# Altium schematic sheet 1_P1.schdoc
size 307 x 218 mm; Symbol: Drawing-Symbol_A4; Device: Drawing-Symbol_A4; @Project Name: OpenSteamDeck ButtonPCB; @Page Count: 1; @Update Date: 2025-07-23; @Create Date: 2025-07-02; @Schematic Name: Schematic1; @Page No: 1; @Page Name: P1; Company: EasyEDA.com; Version: V1.0; Page Size: A4; @Create Time: 10:19:51; @Update Time: 22:36:55; Width: 1170; Height: 825; Region Start: 1; X Region Count: 6; Y Region Count: 4; Blade Width: 10; Title Block Position: 3; @Board Name: Board1
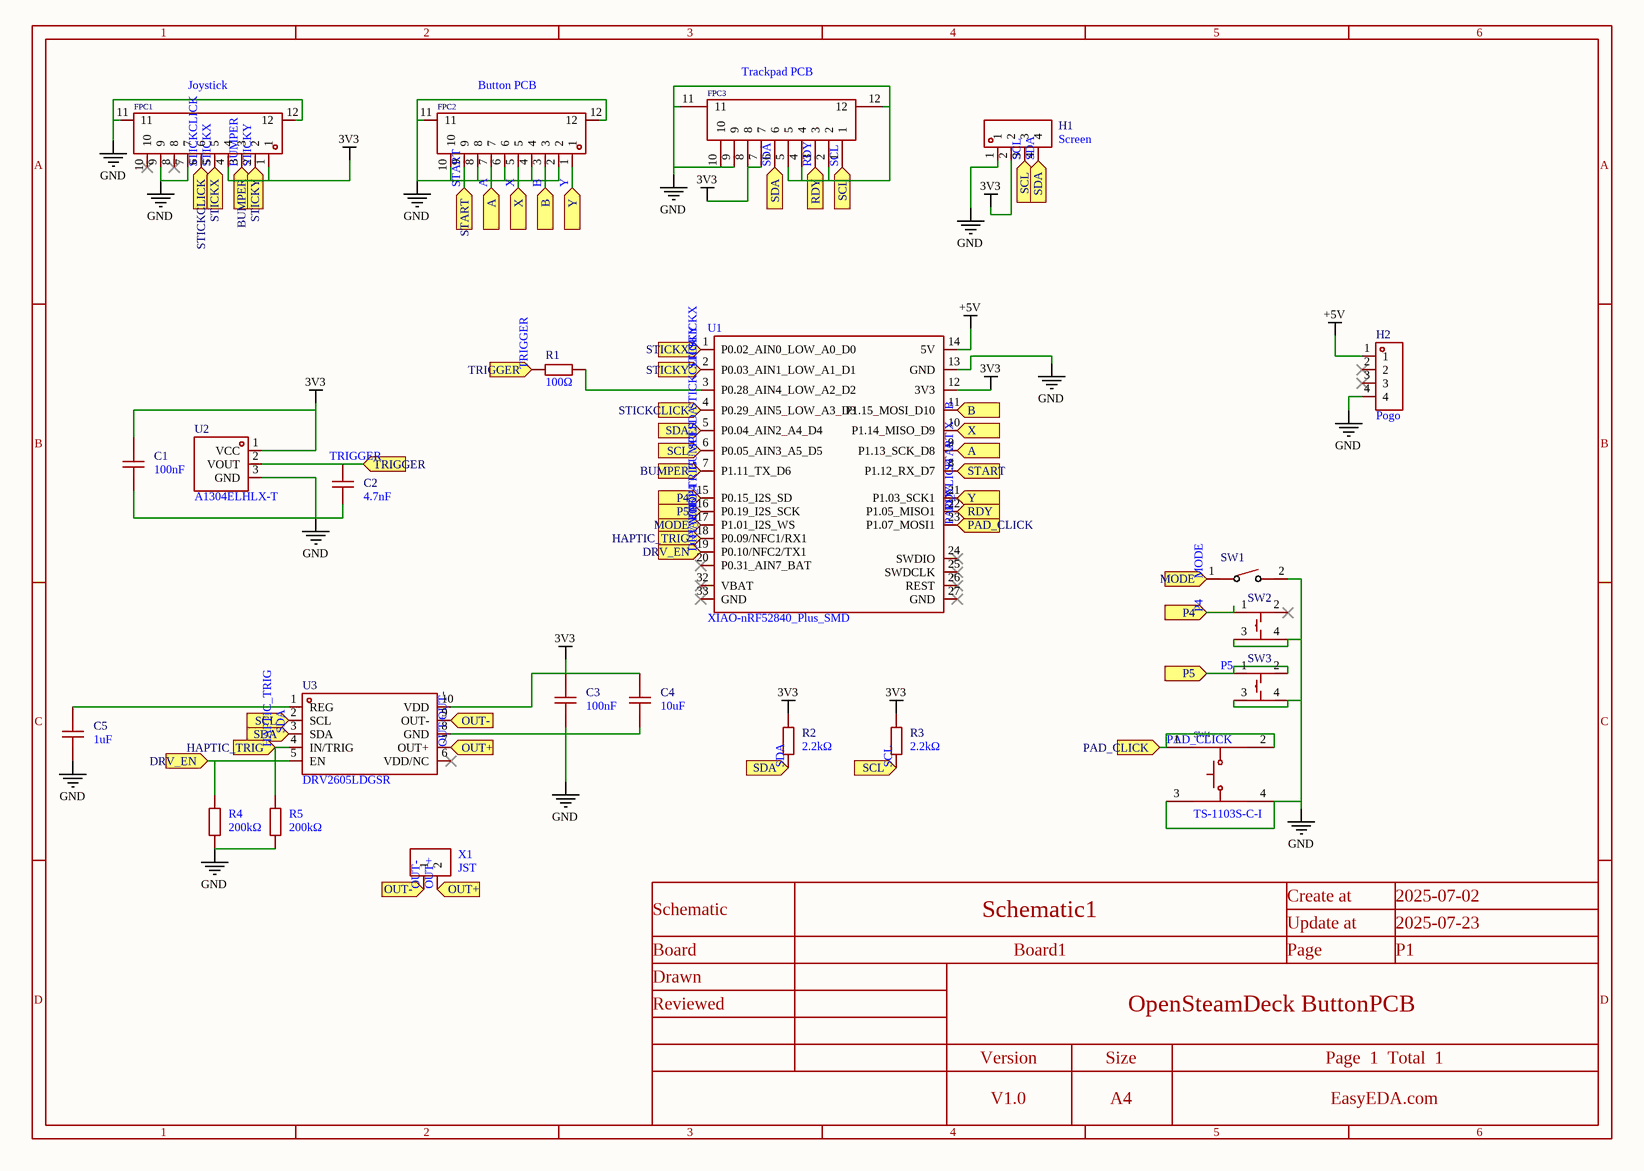
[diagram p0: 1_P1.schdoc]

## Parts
C1  100nF  [C0603]
C2  4.7nF  [C0603]
C3  100nF  [C0603]
C4  10uF  [C0603]
C5  1uF  [C0603]
FPC1  Joystick  [FPC-SMD_10P-P0.50_XUNPU_FPC-05F-10PH15]
FPC2  Button PCB  [FPC-SMD_10P-P0.50_XUNPU_FPC-05F-10PH15]
FPC3  Trackpad PCB  [FPC-SMD_P0.50-10P_LCS-SJ-H2.0]
H1  Screen  [HDR-TH_4P-P2.54-V-F]
H2  Pogo  [HDR-TH_4P-P2.54-V-F]
R1  100Ω  [R0603]
R2  2.2kΩ  [R0603]
R3  2.2kΩ  [R0603]
R4  200kΩ  [R0603]
R5  200kΩ  [R0603]
SW1  Start  [SW-SMD_L3.9-W3.0-P4.45]  (value not drawn)
SW2  EVPBFAC1A000  [KEY-SMD_4P-L6.0-W6.0-P4.00-LS6.6]  (value not drawn)
SW3  EVPBFAC1A000  [KEY-SMD_4P-L6.0-W6.0-P4.00-LS6.6]  (value not drawn)
SW4  TS-1103S-C-I  [KEY-SMD_4P-L12.0-W12.0-P5.00-LS15.4]
U1  XIAO-nRF52840_Plus_SMD  [XIAO-nRF52840-Plus-SMD]
U2  A1304ELHLX-T  [SOT-23-3_L3.0-W1.9-P0.95-LS2.9-BL]
U3  DRV2605LDGSR  [VSSOP-10_L3.0-W3.0-P0.50-LS4.9-BL]
X1  JST  [2JST2.54]

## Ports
A (in), B (in), BUMPER (in), DRV_EN (in), HAPTIC_TRIG (in), MODE (in), OUT+ (in), OUT- (in), P4 (in), P5 (in), PAD_CLICK (in), RDY (in), SCL (in), SDA (in), START (in), STICKCLICK (in), STICKX (in), STICKY (in), TRIGGER (in), X (in), Y (in)

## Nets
3V3: C1.2 C3.2 C4.2 FPC1.1 FPC1.4 FPC3.7 FPC3.8 H1.2 R2.2 R3.2 U1.12(3V3) U2.1(VCC) U3.10(VDD)
+5V: H2.1 U1.14(5V)
GND: C1.1 C2.1 C3.1 C4.1 C5.1 FPC1.7 FPC1.9 FPC1.11 FPC1.12 FPC2.2 FPC2.4 FPC2.6 FPC2.8 FPC2.10 FPC2.11 FPC2.12 FPC3.2 FPC3.4 FPC3.5 FPC3.9 FPC3.10 FPC3.11 FPC3.12 H1.1 H2.4 R4.1 R5.1 SW1.2 SW2.3(A&apos;) SW2.4(A) SW3.3(A&apos;) SW3.4(A) SW4.3 SW4.4 U1.13(GND) U2.3(GND) U3.8(GND)
A: FPC2.7 U1.9(P1.13_SCK_D8) ; port A
B: FPC2.3 U1.11(P1.15_MOSI_D10) ; port B
BUMPER: FPC1.3 U1.7(P1.11_TX_D6) ; port BUMPER
DRV_EN: R4.2 U1.19(P0.10/NFC2/TX1) U3.5(EN) ; port DRV_EN
HAPTIC_TRIG: R5.2 U1.18(P0.09/NFC1/RX1) U3.4(IN/TRIG) ; port HAPTIC_TRIG
MODE: SW1.1 U1.17(P1.01_I2S_WS) ; port MODE
OUT+: U3.7(OUT+) X1.2 ; port OUT+
OUT-: U3.9(OUT-) X1.1 ; port OUT-
P4: SW2.1(B&apos;) U1.15(P0.15_I2S_SD) ; port P4
P5: SW3.1(B&apos;) SW3.2(B) U1.16(P0.19_I2S_SCK) ; port P5
PAD_CLICK: SW4.1 SW4.2 U1.23(P1.07_MOSI1) ; port PAD_CLICK
RDY: FPC3.3 U1.22(P1.05_MISO1) ; port RDY
SCL: FPC3.1 H1.3 R3.1 U1.6(P0.05_AIN3_A5_D5) U3.2(SCL) ; port SCL
SDA: FPC3.6 H1.4 R2.1 U1.5(P0.04_AIN2_A4_D4) U3.3(SDA) ; port SDA
START: FPC2.9 U1.8(P1.12_RX_D7) ; port START
STICKCLICK: FPC1.6 U1.4(P0.29_AIN5_LOW_A3_D3) ; port STICKCLICK
STICKX: FPC1.5 U1.1(P0.02_AIN0_LOW_A0_D0) ; port STICKX
STICKY: FPC1.2 U1.2(P0.03_AIN1_LOW_A1_D1) ; port STICKY
TRIGGER: C2.2 R1.1 U2.2(VOUT) ; port TRIGGER
X: FPC2.5 U1.10(P1.14_MISO_D9) ; port X
Y: FPC2.1 U1.21(P1.03_SCK1) ; port Y
NetC5_2: C5.2 U3.1(REG)
NetR1_2: R1.2 U1.3(P0.28_AIN4_LOW_A2_D2)

Not connected (* = marked no-connect by the designer): FPC1 8* 10*; H2 2* 3*; SW2 2(B)*; U1 20(P0.31_AIN7_BAT)* 24(SWDIO)* 25(SWDCLK)* 26(REST)* 27(GND)* 32(VBAT)* 33(GND)*; U3 6(VDD/NC)*

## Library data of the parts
C1 C3 = CC0603KRX7R9BB104: Manufacturer: YAGEO(国巨); Add into BOM: yes; Tolerance: ±10%; Voltage Rating: 50V; Temperature Coefficient: X7R
C2 = 0603B472K500NT: Manufacturer: FH(风华); Add into BOM: yes; Tolerance: ±10%; Voltage Rating: 50V; Temperature Coefficient: X7R
C4 = CL10A106KP8NNNC: Manufacturer: SAMSUNG(三星); Add into BOM: yes; Tolerance: ±10%
C5 = CL10A105KB8NNNC: Manufacturer: SAMSUNG(三星); Add into BOM: yes; Tolerance: ±10%
FPC1 FPC2 = FPC-05F-10PH15: Manufacturer: XUNPU(讯普); Add into BOM: yes; Locking Feature: Clamshell; Number of Contacts: 10P; Pitch: 0.5mm; FFC, FCB Thickness: 0.3mm
FPC3 = AFC07-S10ECC-00: Manufacturer: JS(钜硕电子); Add into BOM: yes; Locking Feature: 抽屉式; Number of Contacts: 10P; Pitch: 0.5mm; FFC, FCB Thickness: 0.3mm
H1 H2 = PM254V-11-04-H85: Manufacturer: XFCN(兴飞); Add into BOM: yes; Holes Structure: 1x4P; Pitch: 2.54mm; Number of Holes: 4P
R1 = 0603WAF1000T5E: Manufacturer: UNI-ROYAL(厚声); Add into BOM: yes; Tolerance: ±1%; Temperature Coefficient: ±200ppm/℃
R2 R3 = 0603WAF2201T5E_C4190: Manufacturer: UNI-ROYAL(厚声); Add into BOM: yes; Tolerance: ±1%; Temperature Coefficient: ±100ppm/℃
R4 R5 = 0603WAF2003T5E: Manufacturer: UNI-ROYAL(厚声); Add into BOM: yes; Tolerance: ±1%; Power(Watts): 100mW; Temperature Coefficient: ±100ppm/℃; Overload Voltage (Max): 75V
SW1 = TS-1088-AR02016: Manufacturer: XUNPU(讯普); Add into BOM: yes; Circuit: SPST; Actuator Style: Round Button; Operating Force: 160gf; Switch Length: 4mm; Switch Width: 3mm; Switch Height: 2mm; Strike Gundam: 不带; Contact Current: 50mA; Voltage Rating (DC): 12V; Insulation Resistance: 100MΩ; Actuator/Cap Color: Black; Pin Style: SMDSplicing; Mechanical Life: 10万次
SW2 SW3 = EVPBFAC1A000: Manufacturer: PANASONIC(松下); Add into BOM: yes; Circuit: SPST; Actuator Style: Round Button; Operating Force: 2N; Switch Length: 6mm; Switch Height: 3.5mm; Contact Current: 20mA; Voltage Rating (DC): 15V; Insulation Resistance: 100MΩ; Actuator/Cap Color: Gray; Pin Style: J pin; Mechanical Life: 100万次
SW4 = TS-1103S-C-I: Manufacturer: XKB Connectivity(中国星坤); Add into BOM: yes; Circuit: SPST; Actuator Style: Round Button; Operating Force: 260gf; Switch Length: 12mm; Switch Height: 8mm; Strike Gundam: 不带; Contact Current: 50mA; Voltage Rating (DC): 12V; Actuator/Cap Color: Black; With Lamp: No; Mechanical Life: 20万次
U1 = XIAO-nRF52840_Plus_SMD: Add into BOM: yes
U2 = A1304ELHLX-T: Manufacturer: ALLEGRO(美国埃戈罗); Add into BOM: yes; supply voltage: 3V~3.6V
U3 = DRV2605LDGSR: Manufacturer: TI(德州仪器); Add into BOM: yes; Interface: I2C
X1 = JST: Add into BOM: yes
